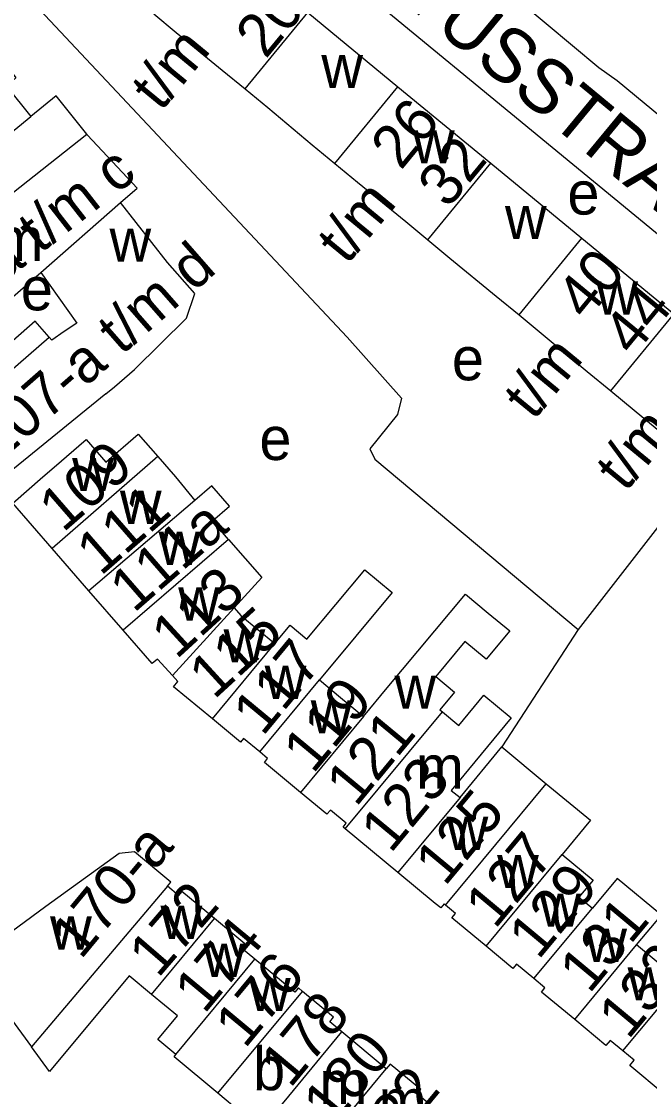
# Model space of a CAD drawing. Extents: x 161141 to 163125, y 381621 to 383200.
# Drawn here: x 162324.6 to 162382.8, y 381942.6 to 382042.2 of the extents above; entities that cross this region are included whole.
import ezdxf

# ---------------------------------------------------------------- set-up
doc = ezdxf.new("R2010")
doc.units = 0
for name, color, linetype in [('BLT_Basislijn', 7, 'Continuous'), ('BLT_Bebouwing', 7, 'Continuous'), ('BLT_Centroide', 7, 'Continuous'), ('BLT_Huisnummer', 7, 'Continuous'), ('BLT_Huisnummer_ tussenligend', 7, 'Continuous'), ('BLT_Huisnummer_reeks', 7, 'Continuous'), ('BLT_Onderverdeling_panden', 7, 'Continuous'), ('BLT_Straatnaam', 7, 'Continuous')]:
    doc.layers.add(name, color=color, linetype=linetype)

msp = doc.modelspace()

# ---------------------------------------------------------------- linework, layer by layer
at = {"layer": 'BLT_Basislijn'}
for p, q in [((162387.927, 382000.91), (162376.241, 381985.847)), ((162376.241, 381985.847), (162369.166, 381974.973))]:
    msp.add_line(p, q, dxfattribs=at)
for points in [[(162334.15, 382074.254), (162337.26, 382071.57), (162358.618, 382054.299), (162378.152, 382037.958), (162379.854, 382036.766), (162386.453, 382031.277), (162396.073, 382023.678), (162401.709, 382018.711), (162402.151, 382018.356)], [(162328.752, 382067.801), (162332.192, 382064.856), (162396.799, 382011.676)], [(162319.842, 382056.942), (162318.879, 382055.827), (162318.879, 382055.189), (162324.45, 382045.342), (162354.824, 382012.967), (162359.855, 382007.305), (162359.472, 382005.807), (162356.922, 382002.62), (162357.4, 382001.663), (162376.241, 381985.847)]]:
    msp.add_lwpolyline(points, dxfattribs=at)
at = {"layer": 'BLT_Bebouwing'}
for p, q in [((162351.163, 382043.052), (162359.529, 382036.166)), ((162359.529, 382036.166), (162368.139, 382029.079)), ((162368.139, 382029.079), (162376.587, 382022.126)), ((162376.587, 382022.126), (162385.109, 382015.112)), ((162321.035, 382014.266), (162326.408, 382018.961)), ((162326.408, 382018.961), (162329.765, 382014.253)), ((162327.471, 381993.383), (162323.824, 381997.579)), ((162330.886, 381989.449), (162327.471, 381993.383)), ((162334.062, 381985.793), (162330.886, 381989.449)), ((162365.281, 381970.278), (162369.166, 381974.973)), ((162369.166, 381974.973), (162373.282, 381971.567)), ((162362.979, 381960.47), (162359.517, 381963.336)), ((162326.899, 381960.173), (162319.836, 381955.026)), ((162385.724, 381953.229), (162381.652, 381956.614)), ((162349.959, 381952.224), (162346.276, 381955.285)), ((162358.433, 381945.137), (162354.33, 381948.548))]:
    msp.add_line(p, q, dxfattribs=at)
for points in [[(162336.898, 382042.931), (162338.981, 382041.217), (162343.243, 382037.727), (162345.351, 382035.992)], [(162322.494, 382039.162), (162324.105, 382037.011), (162323.225, 382036.241), (162325.489, 382033.411)], [(162345.351, 382035.992), (162347.46, 382034.256), (162351.584, 382030.801), (162353.688, 382029.069)], [(162330.679, 382031.784), (162327.85, 382035.326), (162325.489, 382033.411)], [(162333.823, 382025.44), (162335.362, 382026.784), (162330.749, 382031.696), (162330.679, 382031.784)], [(162353.688, 382029.069), (162355.793, 382027.337), (162360.251, 382023.673), (162362.299, 382021.987)], [(162332.443, 382007.709), (162333.242, 382008.36), (162335.119, 382009.976), (162339.928, 382014.736), (162340.698, 382016.995), (162338.175, 382019.878), (162333.823, 382025.44)], [(162362.299, 382021.987), (162364.348, 382020.3), (162368.637, 382016.777), (162370.752, 382015.036)], [(162370.752, 382015.036), (162377.073, 382009.78), (162379.248, 382007.99)], [(162327.189, 382012.966), (162325.908, 382014.432), (162323.065, 382011.945), (162321.035, 382014.266)], [(162329.765, 382014.253), (162328.596, 382013.473)], [(162328.596, 382013.473), (162327.428, 382012.693), (162327.189, 382012.966)], [(162332.443, 382007.709), (162326.13, 382002.566), (162322.981, 382000), (162322.239, 381999.395)], [(162379.248, 382007.99), (162381.423, 382006.2), (162385.669, 382002.699), (162387.927, 382000.91)], [(162323.824, 381997.579), (162326.611, 382000), (162327.649, 382000.897), (162330.615, 382003.474), (162332.447, 382001.364), (162335.452, 382003.974), (162337.264, 382001.889)], [(162337.264, 382001.889), (162338.906, 382000), (162340.697, 381997.817)], [(162343.833, 381994.208), (162342.333, 381995.934), (162343.905, 381997.299), (162342.269, 381999.183), (162340.697, 381997.817)], [(162343.833, 381994.208), (162346.902, 381990.676), (162344.337, 381987.867)], [(162348.116, 381984.548), (162349.531, 381986.253), (162351.093, 381984.955), (162356.443, 381991.401), (162358.982, 381989.294), (162352.251, 381981.184)], [(162356.335, 381977.804), (162358.526, 381980.451), (162365.776, 381989.13), (162367.898, 381987.373), (162369.884, 381985.729), (162367.712, 381983.105), (162365.726, 381984.749), (162363.031, 381981.494), (162364.77, 381980.055), (162363.42, 381978.425), (162363.655, 381978.23)], [(162344.337, 381987.867), (162344.949, 381987.17), (162348.116, 381984.548)], [(162338.614, 381981.599), (162337.232, 381983.109), (162336.754, 381982.694), (162334.062, 381985.793)], [(162342.323, 381977.569), (162338.731, 381980.542), (162339.136, 381981.03), (162338.614, 381981.599)], [(162352.251, 381981.184), (162354.21, 381979.563), (162356.335, 381977.804)], [(162363.655, 381978.23), (162365.179, 381976.969), (162367.491, 381979.763), (162370.033, 381977.658), (162364.475, 381970.946), (162365.281, 381970.278)], [(162346.715, 381974.514), (162345.224, 381975.748), (162344.938, 381975.403), (162342.323, 381977.569)], [(162350.501, 381970.756), (162347.142, 381973.537), (162347.448, 381973.907), (162346.715, 381974.514)], [(162373.282, 381971.567), (162377.383, 381968.174), (162374.762, 381965.007)], [(162354.722, 381967.913), (162353.264, 381969.12), (162352.944, 381968.733), (162350.501, 381970.756)], [(162354.643, 381967.373), (162354.439, 381967.542), (162354.722, 381967.913)], [(162359.517, 381963.336), (162354.643, 381967.373)], [(162338.159, 381962.071), (162338.463, 381962.436), (162335.091, 381965.239), (162333.67, 381965.108), (162326.899, 381960.173)], [(162374.762, 381965.007), (162377.625, 381962.637), (162376.299, 381961.035), (162377.551, 381960.02)], [(162342.53, 381959.056), (162339.504, 381961.571), (162339.2, 381961.206), (162338.159, 381962.071)], [(162381.652, 381956.614), (162383.946, 381959.377), (162379.844, 381962.782), (162377.551, 381960.02)], [(162363.931, 381960.306), (162363.801, 381960.414), (162363.494, 381960.043), (162362.979, 381960.47)], [(162367.692, 381956.491), (162364.52, 381959.117), (162364.865, 381959.533), (162363.931, 381960.306)], [(162346.276, 381955.285), (162345.017, 381956.332), (162345.34, 381956.72), (162342.53, 381959.056)], [(162372.135, 381953.497), (162370.516, 381954.837), (162370.179, 381954.431), (162367.692, 381956.491)], [(162319.836, 381955.026), (162322.781, 381950.985), (162325.568, 381947.162)], [(162336.696, 381952.03), (162334.613, 381953.761), (162327.231, 381944.881), (162325.568, 381947.162)], [(162375.912, 381949.7), (162372.824, 381952.254), (162373.154, 381952.653), (162372.135, 381953.497)], [(162338.95, 381946.461), (162337.27, 381947.857), (162339.085, 381950.043), (162336.696, 381952.03)], [(162350.687, 381952.316), (162350.302, 381952.636), (162349.959, 381952.224)], [(162354.33, 381948.548), (162353.198, 381949.489), (162353.562, 381949.926), (162350.687, 381952.316)], [(162380.367, 381946.792), (162379.189, 381947.768), (162378.804, 381947.303), (162375.912, 381949.7)], [(162342.844, 381942.87), (162338.777, 381946.252), (162338.95, 381946.461)], [(162384.217, 381942.776), (162381.013, 381945.43), (162381.42, 381945.921), (162380.367, 381946.792)], [(162362.519, 381941.792), (162361.306, 381942.801), (162361.644, 381943.208), (162358.797, 381945.575), (162358.433, 381945.137)], [(162344.855, 381937.071), (162342.915, 381938.666), (162344.241, 381940.239), (162344.956, 381941.087), (162342.844, 381942.87)]]:
    msp.add_lwpolyline(points, dxfattribs=at)
at = {"layer": 'BLT_Onderverdeling_panden'}
for p, q in [((162345.351, 382035.992), (162351.163, 382043.052)), ((162353.688, 382029.069), (162359.529, 382036.166)), ((162306.198, 382017.76), (162325.489, 382033.411)), ((162321.479, 382024.508), (162330.679, 382031.784)), ((162362.299, 382021.987), (162368.139, 382029.079)), ((162326.408, 382018.961), (162333.823, 382025.44)), ((162370.752, 382015.036), (162376.587, 382022.126)), ((162379.248, 382007.99), (162385.109, 382015.112)), ((162317.658, 382004.641), (162327.189, 382012.966)), ((162337.264, 382001.889), (162327.471, 381993.383)), ((162340.697, 381997.817), (162330.886, 381989.449)), ((162343.833, 381994.208), (162334.062, 381985.793)), ((162338.614, 381981.599), (162344.337, 381987.867)), ((162342.323, 381977.569), (162348.116, 381984.548)), ((162346.715, 381974.514), (162352.251, 381981.184)), ((162354.643, 381967.373), (162363.655, 381978.23)), ((162356.335, 381977.804), (162350.501, 381970.756)), ((162363.931, 381960.306), (162373.282, 381971.567)), ((162365.281, 381970.278), (162359.517, 381963.336)), ((162367.692, 381956.491), (162374.762, 381965.007)), ((162338.159, 381962.071), (162325.568, 381947.162)), ((162372.135, 381953.497), (162377.551, 381960.02)), ((162336.696, 381952.03), (162342.53, 381959.056)), ((162375.912, 381949.7), (162381.652, 381956.614)), ((162338.95, 381946.461), (162346.276, 381955.285)), ((162380.367, 381946.792), (162385.724, 381953.229)), ((162342.844, 381942.87), (162350.687, 381952.316)), ((162344.855, 381937.071), (162354.33, 381948.548)), ((162349.38, 381934.229), (162358.433, 381945.137))]:
    msp.add_line(p, q, dxfattribs=at)

# ---------------------------------------------------------------- texts
at = {"layer": 'BLT_Centroide'}
for s, p in [('w', (162352.422, 382036.062)), ('w', (162360.914, 382029.062)), ('e', (162375.238, 382024.327)), ('w', (162369.445, 382022.062)), ('m', (162322.211, 382020.031)), ('w', (162332.789, 382019.96)), ('e', (162324.567, 382015.449)), ('w', (162377.914, 382015.062)), ('e', (162364.528, 382008.962)), ('e', (162346.683, 382001.572)), ('w', (162329.328, 381998.688)), ('w', (162333.75, 381995.656)), ('w', (162337.344, 381991.844)), ('w', (162339.164, 381986.688)), ('w', (162343.359, 381982.812)), ('w', (162347.172, 381979.422)), ('w', (162359.203, 381978.516)), ('w', (162351.438, 381976.234)), ('m', (162361.188, 381971.109)), ('w', (162364.031, 381965.422)), ('w', (162368.719, 381961.891)), ('w', (162372.656, 381958.297)), ('w', (162337.516, 381957.172)), ('w', (162327.281, 381956.188)), ('w', (162376.891, 381955.047)), ('w', (162341.484, 381953.656)), ('w', (162380.812, 381951.484)), ('w', (162345.719, 381950.484)), ('b', (162346.096, 381943.151)), ('m', (162352.234, 381941.859)), ('m', (162357.734, 381940.156))]:
    msp.add_text(s, height=4, dxfattribs=at).set_placement(p)
at = {"layer": 'BLT_Huisnummer'}
for s, rotation, p in [('109', 40.98086, (162328.482, 381994.783)), ('111', 40.99938, (162331.966, 381990.756)), ('111a', 40.98086, (162335.04, 381987.331)), ('113', 42.48737, (162338.989, 381983.026)), ('117', 50.38366, (162346.993, 381975.877)), ('121', 50.39444, (162355.641, 381969.32)), ('125', 50.2342, (162363.882, 381961.971)), ('129', 50.23084, (162372.548, 381955.154)), ('174', 50.26246, (162341.571, 381950.128)), ('133', 50.23036, (162380.874, 381947.758)), ('178', 50.26357, (162349.536, 381943.25)), ('182', 50.26357, (162357.88, 381936.287))]:
    msp.add_text(s, height=4, rotation=rotation, dxfattribs=at).set_placement(p)
at = {"layer": 'BLT_Huisnummer_ tussenligend'}
for s, rotation, p in [('115', 42.48737, (162342.479, 381979.3)), ('119', 50.38366, (162351.652, 381972.39)), ('123', 50.39444, (162358.846, 381965.017)), ('127', 50.2342, (162368.526, 381958.002)), ('172', 49.25731, (162337.294, 381953.465)), ('131', 50.23084, (162377.259, 381952.009)), ('176', 50.26246, (162345.339, 381946.923)), ('180', 50.26357, (162353.487, 381939.662))]:
    msp.add_text(s, height=4, rotation=rotation, dxfattribs=at).set_placement(p)
at = {"layer": 'BLT_Huisnummer_reeks'}
for s, rotation, p in [('20', 50.54176, (162347.265, 382038.675)), ('t/m', 50.54481, (162337.557, 382033.8)), ('26', 50.54481, (162359.8, 382028.354)), ('32', 50.53377, (162364.159, 382024.788)), ('103-a t/m c', 38.02416, (162314.401, 382011.311)), ('t/m', 50.54481, (162354.803, 382019.593)), ('107-a t/m d', 41.17056, (162322.491, 382001.253)), ('40', 50.54596, (162376.992, 382014.395)), ('44', 50.54757, (162381.333, 382011.074)), ('t/m', 50.54596, (162372.1, 382005.163)), ('t/m', 50.54596, (162380.625, 381998.521)), ('170-a', 50.26538, (162330.129, 381955.176))]:
    msp.add_text(s, height=4, rotation=rotation, dxfattribs=at).set_placement(p)
at = {"layer": 'BLT_Straatnaam'}
msp.add_text('ST HUBERTUSSTRAAT', height=5, rotation=320.43053, dxfattribs=at).set_placement((162333.591, 382065.815))

doc.saveas('drawing.dxf')
